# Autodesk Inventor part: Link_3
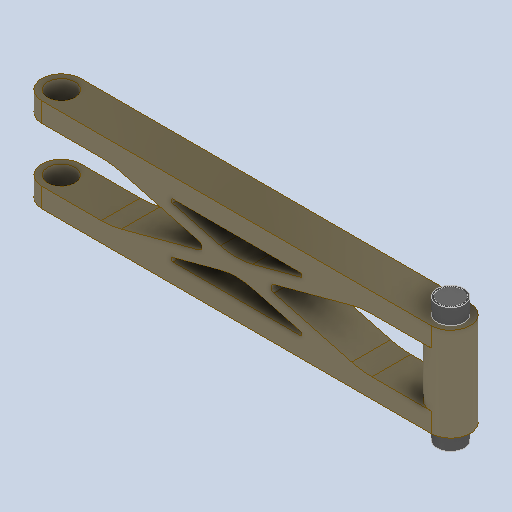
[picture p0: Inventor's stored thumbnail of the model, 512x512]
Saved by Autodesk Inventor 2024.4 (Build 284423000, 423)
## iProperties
Created: 2025-07
Part Number: Link_3
Material: Generic
Document SubType Name: Modeling
Designer: AdminForWorker
Density: 1 g/cm^3
Appearance: Default
Title: Link_3 v3
Author: AdminForWorker
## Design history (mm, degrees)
feature "Body2"
feature "Body3"
feature "Body4"
feature "Body5"
feature "Body6"
body "Solid1"
body "Solid2"
body "Solid3"
body "Solid4"
body "Solid5"
